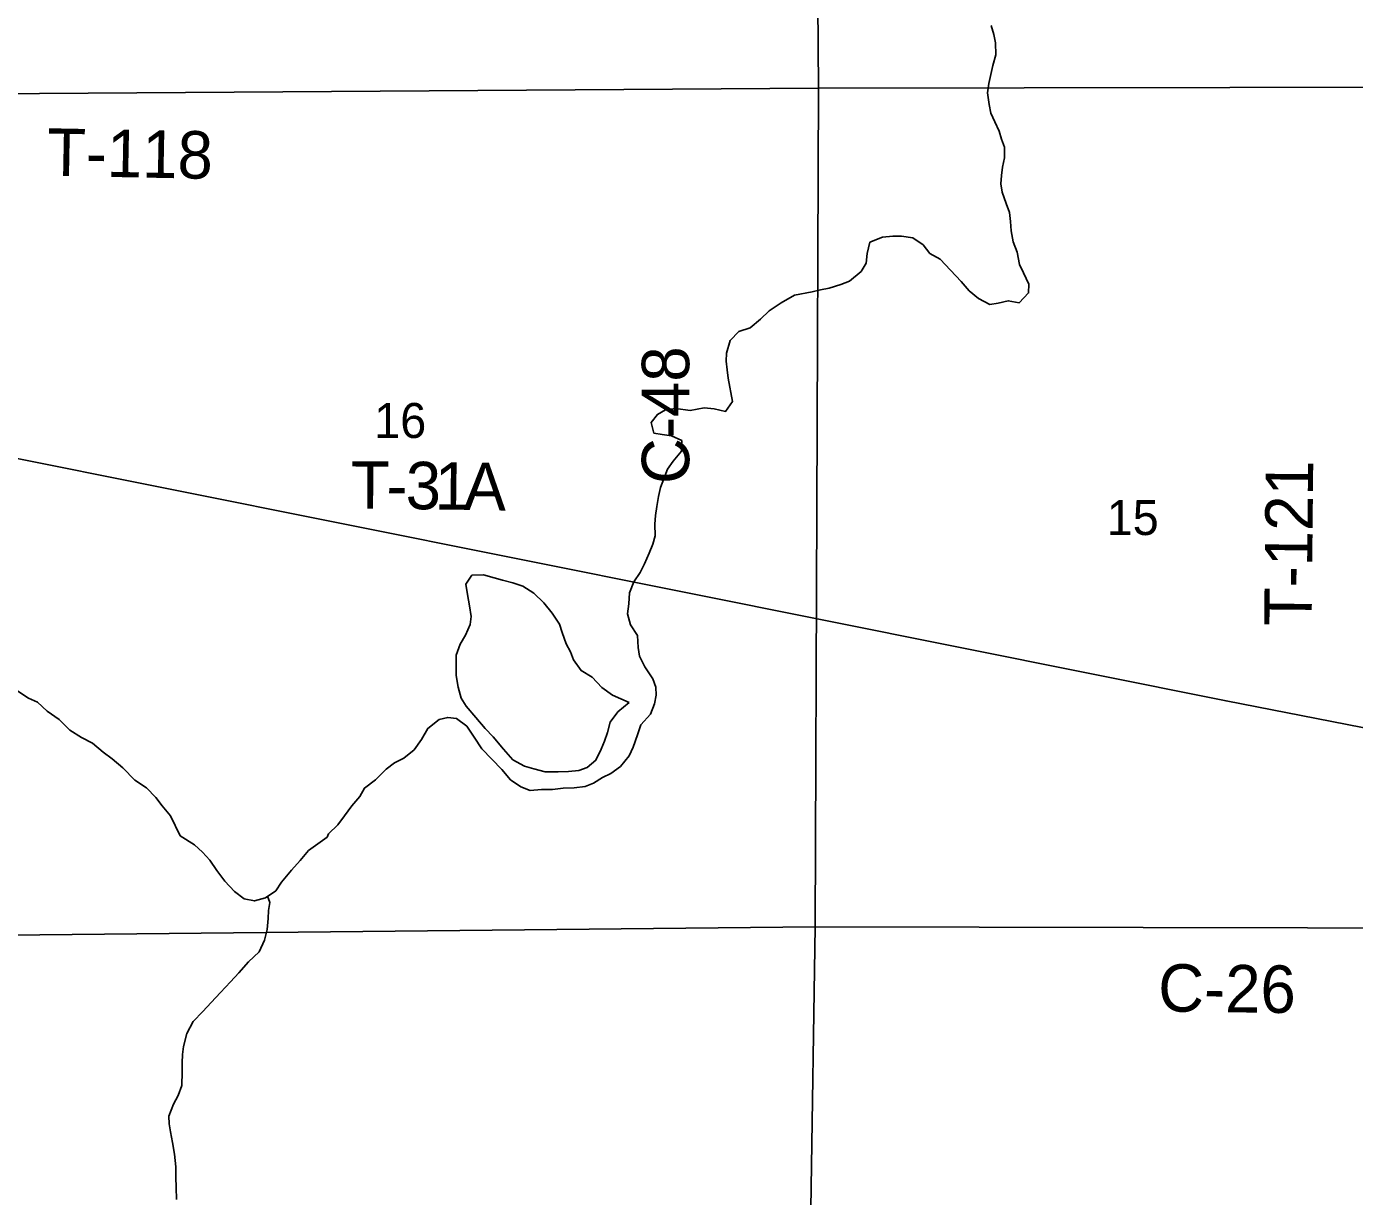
# Model space of a CAD drawing. Extents: x 1772825 to 1773716, y 1138558 to 1139032.
# Drawn here: x 1772826.028 to 1772826.822, y 1138562.479 to 1138563.179 of the extents above; entities that cross this region are included whole.
import ezdxf

# ---------------------------------------------------------------- set-up
doc = ezdxf.new("R2010")
doc.units = 0
for name, color, linetype in [('GM_X_County_Road_Text', 7, 'Continuous'), ('GM_X_Minor_Lake', 7, 'Continuous'), ('GM_X_Minor_River', 7, 'Continuous'), ('GM_X_Rail_Line', 7, 'Continuous'), ('GM_X_Section', 7, 'Continuous'), ('GM_X_Section_Text', 7, 'Continuous'), ('GM_X_Township_Road_Text', 7, 'Continuous')]:
    doc.layers.add(name, color=color, linetype=linetype)

msp = doc.modelspace()

# ---------------------------------------------------------------- linework, layer by layer
at = {"layer": 'GM_X_Minor_Lake'}
for points in [[(1772826.37848, 1138562.77863), (1772826.37206, 1138562.78322), (1772826.36621, 1138562.78932), (1772826.35959, 1138562.79333), (1772826.35507, 1138562.7998), (1772826.3532, 1138562.80455), (1772826.35076, 1138562.80931), (1772826.34832, 1138562.81615), (1772826.34664, 1138562.82109), (1772826.34231, 1138562.82756), (1772826.33741, 1138562.83384), (1772826.33137, 1138562.83956), (1772826.32476, 1138562.84377), (1772826.3187, 1138562.84588), (1772826.31264, 1138562.84743), (1772826.30754, 1138562.84878), (1772826.30129, 1138562.85052), (1772826.29428, 1138562.85036), (1772826.29066, 1138562.84507), (1772826.29158, 1138562.8388), (1772826.29287, 1138562.83197), (1772826.29379, 1138562.8257), (1772826.2932, 1138562.82078), (1772826.29052, 1138562.81453), (1772826.28728, 1138562.80904), (1772826.28479, 1138562.8026), (1772826.28495, 1138562.7954), (1772826.28493, 1138562.79027), (1772826.28603, 1138562.78344), (1772826.2879, 1138562.77679), (1772826.29091, 1138562.77203), (1772826.29657, 1138562.76518), (1772826.30222, 1138562.7587), (1772826.30694, 1138562.75356), (1772826.31316, 1138562.74632), (1772826.31882, 1138562.73984), (1772826.32581, 1138562.73601), (1772826.3313, 1138562.73447), (1772826.33811, 1138562.73273), (1772826.34588, 1138562.73269), (1772826.35214, 1138562.73285), (1772826.3582, 1138562.73358), (1772826.36333, 1138562.73527), (1772826.36846, 1138562.73961), (1772826.37171, 1138562.74623), (1772826.37363, 1138562.75115), (1772826.37535, 1138562.75627), (1772826.37708, 1138562.76252), (1772826.38166, 1138562.76857), (1772826.38835, 1138562.77426)], [(1772826.38835, 1138562.77426), (1772826.37848, 1138562.77863)]]:
    msp.add_lwpolyline(points, dxfattribs=at)
at = {"layer": 'GM_X_Minor_River'}
for points in [[(1772826.60508, 1138563.17921), (1772826.60656, 1138563.17389), (1772826.60767, 1138563.16895), (1772826.60781, 1138563.16173), (1772826.60607, 1138563.15529), (1772826.60373, 1138563.14467), (1772826.60294, 1138563.13898), (1772826.60384, 1138563.13195), (1772826.60476, 1138563.12682), (1772826.60719, 1138563.12168), (1772826.6098, 1138563.11597), (1772826.61129, 1138563.11122), (1772826.61296, 1138563.10646), (1772826.61292, 1138563.10019), (1772826.61175, 1138563.09451), (1772826.61115, 1138563.08957), (1772826.61074, 1138563.08445), (1772826.61166, 1138563.07951), (1772826.61408, 1138563.07285), (1772826.61594, 1138563.06733), (1772826.61667, 1138563.06201), (1772826.61701, 1138563.05651), (1772826.6183, 1138563.04986), (1772826.62053, 1138563.04358), (1772826.622, 1138563.03636), (1772826.62443, 1138563.03122), (1772826.62761, 1138563.02455), (1772826.62739, 1138563.01924), (1772826.62186, 1138563.01339), (1772826.61524, 1138563.01456), (1772826.60917, 1138563.01308), (1772826.60424, 1138563.01235), (1772826.59744, 1138563.016), (1772826.59179, 1138563.02059), (1772826.58709, 1138563.02612), (1772826.58069, 1138563.0328), (1772826.57448, 1138563.03948), (1772826.56825, 1138563.04293), (1772826.56431, 1138563.04808), (1772826.55808, 1138563.0523), (1772826.55146, 1138563.05328), (1772826.54616, 1138563.05331), (1772826.54009, 1138563.05259), (1772826.5325, 1138563.0496), (1772826.53075, 1138563.04296), (1772826.53015, 1138563.03708), (1772826.52727, 1138563.03216), (1772826.52023, 1138563.02632), (1772826.51511, 1138563.02426), (1772826.50808, 1138563.02202), (1772826.50296, 1138563.0211), (1772826.49784, 1138563.02), (1772826.48741, 1138563.01797), (1772826.47943, 1138563.01327), (1772826.4722, 1138563.00856), (1772826.46706, 1138563.00347), (1772826.46078, 1138562.99838), (1772826.45413, 1138562.99614), (1772826.4488, 1138562.99086), (1772826.44667, 1138562.98328), (1772826.44645, 1138562.97853), (1772826.44698, 1138562.97321), (1772826.44771, 1138562.96827), (1772826.45028, 1138562.95421), (1772826.44607, 1138562.94835), (1772826.43927, 1138562.94991), (1772826.43321, 1138562.95051), (1772826.42488, 1138562.94896)], [(1772826.20777, 1138562.69365), (1772826.20854, 1138562.6956), (1772826.21406, 1138562.70108), (1772826.21806, 1138562.70637), (1772826.22244, 1138562.71242), (1772826.2272, 1138562.7179), (1772826.23007, 1138562.723), (1772826.23653, 1138562.7279), (1772826.243, 1138562.73432), (1772826.24794, 1138562.73809), (1772826.25364, 1138562.74091), (1772826.25972, 1138562.74582), (1772826.26411, 1138562.75205), (1772826.26793, 1138562.75868), (1772826.27477, 1138562.76395), (1772826.27989, 1138562.76526), (1772826.28501, 1138562.76466), (1772826.29124, 1138562.76008), (1772826.29557, 1138562.75342), (1772826.30028, 1138562.74657), (1772826.30631, 1138562.74028), (1772826.31216, 1138562.73418), (1772826.31744, 1138562.7279), (1772826.32367, 1138562.72369), (1772826.32916, 1138562.72158), (1772826.33598, 1138562.72212), (1772826.34243, 1138562.72209), (1772826.34887, 1138562.72301), (1772826.3555, 1138562.72316), (1772826.36214, 1138562.72389), (1772826.36707, 1138562.72595), (1772826.37239, 1138562.72934), (1772826.37752, 1138562.73178), (1772826.38322, 1138562.73593), (1772826.38837, 1138562.74236), (1772826.39085, 1138562.74747), (1772826.39335, 1138562.75485), (1772826.39546, 1138562.76091), (1772826.40117, 1138562.76715), (1772826.40366, 1138562.77339), (1772826.40463, 1138562.77851), (1772826.40427, 1138562.78344), (1772826.40259, 1138562.78838), (1772826.39769, 1138562.79562), (1772826.39468, 1138562.80189), (1772826.39376, 1138562.80721), (1772826.39341, 1138562.81423), (1772826.38927, 1138562.8207), (1772826.3874, 1138562.82734), (1772826.38819, 1138562.83322), (1772826.38859, 1138562.83986), (1772826.39128, 1138562.84649), (1772826.3949, 1138562.85197), (1772826.39757, 1138562.85708), (1772826.40044, 1138562.86351), (1772826.40255, 1138562.869), (1772826.4039, 1138562.87393), (1772826.40374, 1138562.88095), (1772826.40414, 1138562.88607), (1772826.40492, 1138562.89157), (1772826.40589, 1138562.89744), (1772826.40706, 1138562.90294), (1772826.40916, 1138562.90805), (1772826.41127, 1138562.91373), (1772826.4147, 1138562.91865), (1772826.41965, 1138562.9245), (1772826.41987, 1138562.93095), (1772826.41382, 1138562.93383), (1772826.40814, 1138562.93461), (1772826.40321, 1138562.93539), (1772826.40154, 1138562.94166), (1772826.40535, 1138562.94658), (1772826.4101, 1138562.9494), (1772826.41635, 1138562.95013), (1772826.42488, 1138562.94896)], [(1772826.01442, 1138562.80788), (1772826.01439, 1138562.80124), (1772826.01456, 1138562.79612), (1772826.01644, 1138562.79137), (1772826.01869, 1138562.78623), (1772826.02189, 1138562.78147), (1772826.02888, 1138562.77689), (1772826.03436, 1138562.7744), (1772826.04003, 1138562.76906), (1772826.04721, 1138562.76409), (1772826.05362, 1138562.75761), (1772826.06061, 1138562.75322), (1772826.06723, 1138562.74977), (1772826.07365, 1138562.74443), (1772826.07894, 1138562.74042), (1772826.08536, 1138562.73508), (1772826.09253, 1138562.72764), (1772826.09952, 1138562.72306), (1772826.10518, 1138562.71734), (1772826.10895, 1138562.71239), (1772826.11384, 1138562.7063), (1772826.1198, 1138562.69444)], [(1772826.1198, 1138562.69444), (1772826.12825, 1138562.68905), (1772826.13317, 1138562.68469), (1772826.13752, 1138562.67995), (1772826.14168, 1138562.6737), (1772826.14641, 1138562.66725), (1772826.15227, 1138562.66119), (1772826.15795, 1138562.65664), (1772826.16419, 1138562.6555), (1772826.17081, 1138562.6574), (1772826.17705, 1138562.66157), (1772826.18026, 1138562.6667), (1772826.18631, 1138562.6739), (1772826.19161, 1138562.67959), (1772826.19653, 1138562.68566), (1772826.20777, 1138562.69365)], [(1772826.17207, 1138562.65824), (1772826.17346, 1138562.65456), (1772826.17251, 1138562.64982), (1772826.17232, 1138562.64489), (1772826.17176, 1138562.63844), (1772826.17025, 1138562.63199), (1772826.16703, 1138562.62498), (1772826.1606, 1138562.6191), (1772826.15474, 1138562.61246), (1772826.14982, 1138562.60715), (1772826.14377, 1138562.6007), (1772826.13829, 1138562.59463), (1772826.13318, 1138562.58932), (1772826.12751, 1138562.58325), (1772826.12373, 1138562.57623), (1772826.12165, 1138562.56845), (1772826.12109, 1138562.56353), (1772826.1209, 1138562.5586), (1772826.1209, 1138562.55329), (1772826.12071, 1138562.54513), (1772826.11844, 1138562.53906), (1772826.11579, 1138562.53394), (1772826.11296, 1138562.52674), (1772826.11315, 1138562.522), (1772826.11391, 1138562.51726), (1772826.11504, 1138562.511), (1772826.11637, 1138562.50399), (1772826.11712, 1138562.4964), (1772826.11713, 1138562.49014), (1772826.11732, 1138562.48408), (1772826.11751, 1138562.47687)]]:
    msp.add_lwpolyline(points, dxfattribs=at)
at = {"layer": 'GM_X_Rail_Line'}
msp.add_lwpolyline([(1772825.35791, 1138563.05207), (1772825.61021, 1138563.00197), (1772826.00893, 1138562.92273), (1772826.42335, 1138562.83981), (1772826.74565, 1138562.77515), (1772827.28819, 1138562.66904), (1772827.66667, 1138562.59358), (1772827.92573, 1138562.54123), (1772827.99116, 1138562.52946), (1772828.02, 1138562.52521), (1772828.07408, 1138562.51689), (1772828.14543, 1138562.50583), (1772828.16182, 1138562.50319)], dxfattribs=at)
at = {"layer": 'GM_X_Section'}
for points in [[(1772826.01279, 1138563.64058), (1772826.49778, 1138563.64814), (1772826.50172, 1138563.14184), (1772826.00619, 1138563.13835)], [(1772826.49778, 1138563.64814), (1772826.99889, 1138563.64226), (1772826.99397, 1138563.14266), (1772826.50172, 1138563.14184)], [(1772826.99397, 1138563.14266), (1772826.99058, 1138562.63895), (1772826.49968, 1138562.63999), (1772826.50172, 1138563.14184)], [(1772826.50172, 1138563.14184), (1772826.49968, 1138562.63999), (1772825.99677, 1138562.63482), (1772826.00619, 1138563.13835)], [(1772825.99677, 1138562.63482), (1772826.49968, 1138562.63999), (1772826.49189, 1138562.13379), (1772825.98889, 1138562.13488)], [(1772826.49968, 1138562.63999), (1772826.99058, 1138562.63895), (1772826.98736, 1138562.13574), (1772826.49189, 1138562.13379)]]:
    msp.add_lwpolyline(points, close=True, dxfattribs=at)

# ---------------------------------------------------------------- texts
at = {"layer": 'GM_X_County_Road_Text'}
for s, rotation, p in [('C-48', 90, (1772826.42436, 1138562.90495)), ('C-26', 359.31116, (1772826.70485, 1138562.58935))]:
    msp.add_text(s, height=0.028409, rotation=rotation, dxfattribs=at).set_placement(p)
at = {"layer": 'GM_X_Section_Text'}
for s, p in [('16', (1772826.23584, 1138562.93248)), ('15', (1772826.67417, 1138562.87441))]:
    msp.add_text(s, height=0.020928, rotation=0.00001, dxfattribs=at).set_placement(p)
at = {"layer": 'GM_X_Township_Road_Text'}
for s, height, rotation, p in [('T-118', 0.028409, 358.88696, (1772826.03981, 1138563.08941)), ('T', 0.02841, 359.76523, (1772826.22182, 1138562.89016)), ('3', 0.02841, 359.23899, (1772826.25452, 1138562.88994)), ('1', 0.02841, 359.28211, (1772826.2719, 1138562.88971)), ('A', 0.02841, 358.95936, (1772826.28922, 1138562.88949)), ('T-121', 0.028409, 89.43482, (1772826.79681, 1138562.81978)), ('-', 0.02841, 359.31996, (1772826.24297, 1138562.89008))]:
    msp.add_text(s, height=height, rotation=rotation, dxfattribs=at).set_placement(p)

doc.saveas('drawing.dxf')
